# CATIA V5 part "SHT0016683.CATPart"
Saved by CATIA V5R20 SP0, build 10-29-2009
Part number: SHT0016683
Source: Unknown
Bounding box of the stored display mesh (mm): x 1034.67 to 1473.999, y -744.979 to -680.979, z 40 to 152.7
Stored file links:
  E:\李燕龙\吉利商用车G3\07 设计变更\ECR0009849--标配底支架后移50mm设计变更\数据图纸\SHT0015279-标配底支架左边板\SHT0016683.CATPart
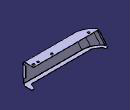
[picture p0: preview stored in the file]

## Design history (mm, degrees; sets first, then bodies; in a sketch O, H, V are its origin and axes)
Body1 "几何体.76" (main body)
  Solid1: solid without history
  RemoveFace1: RemoveFaces (face of Solid1; face of Solid1; face of Solid1; face of Solid1)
